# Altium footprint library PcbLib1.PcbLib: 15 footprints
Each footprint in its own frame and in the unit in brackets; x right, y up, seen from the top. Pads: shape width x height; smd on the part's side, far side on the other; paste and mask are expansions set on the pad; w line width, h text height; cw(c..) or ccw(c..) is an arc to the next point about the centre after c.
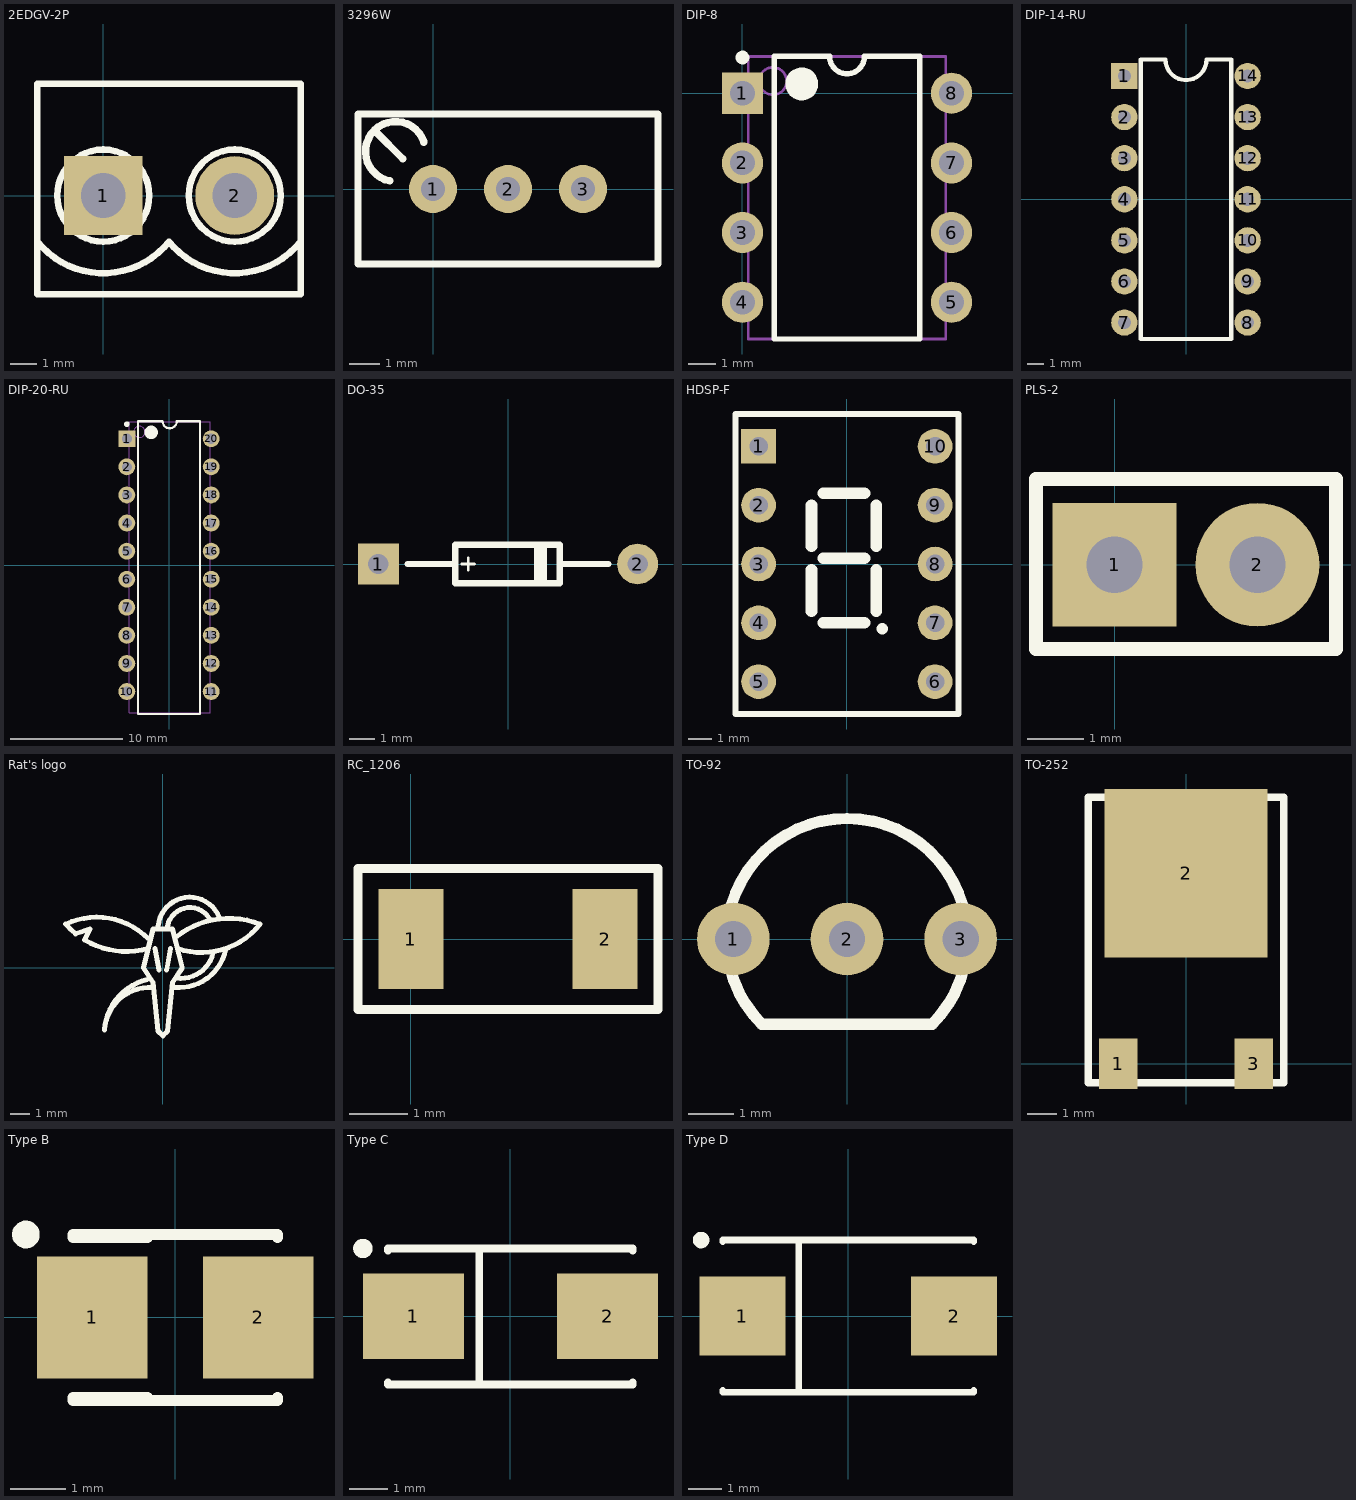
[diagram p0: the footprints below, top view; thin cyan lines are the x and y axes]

## 2EDGV-2P [mm]
height 10
pads (2):
  rect 3x3 hole 1.7: 1(0,0)
  round 3 hole 1.7: 2(5,0)
Top Overlay:
  circle w0.25: c0,0 r1.75
  circle w0.25: c5,0 r1.75
  lines w0.25: -2.5,-3.75 7.5,-3.75 7.5,4.25 -2.5,4.25 -2.5,-3.75
  lines w0.254: -2.499,-1.752 ccw(c0,0.25) 2.499,-1.752 ; 2.501,-1.752 ccw(c5,0.25) 7.499,-1.752
3D body: height 10.22, standoff -2.17, extent -2.725,-3.8 7.525,4

## 3296W [mm]
height 10
pads (3):
  round 1.6 hole 0.8: 1(0,0) 2(2.5,0) 3(5,0)
Top Overlay:
  lines w0.25: -1.905,1.905 -1,1 ; -1.446,0.269 cw(c-1.25,1.25) -0.301,1.566 ; -2.5,-2.5 7.5,-2.5 7.5,2.5 -2.5,2.5 -2.5,-2.5
3D body: height 11.55, standoff -7.62, extent -2.265,-2.415 7.265,2.415

## DIP-8 [mm] "DIP; 8 Leads; Row Spacing 7.62 mm; Pitch 2.54 mm"
height 5.08
pads (8):
  rect 1.5x1.5 hole 0.9: 1(0,0)
  round 1.5 hole 0.9: 2(0,-2.54) 3(0,-5.08) 4(0,-7.62) 5(7.62,-7.62) 6(7.62,-5.08) 7(7.62,-2.54) 8(7.62,0)
Top Overlay:
  circle w0.25: c0,1.3 r0.125
  circle w0.6: c2.16,0.34 r0.3
  lines w0.2: 1.16,-8.96 1.16,1.34 3.175,1.34 ccw(c3.81,1.34) 4.445,1.34 6.46,1.34 6.46,-8.96 1.16,-8.96
Mechanical 13:
  circle w0.1: c1.11,0.44 r0.5
  lines w0.1: 0.21,-8.96 0.21,1.34 7.41,1.34 7.41,-8.96 0.21,-8.96
3D body: height 5.08, standoff -3.5, extent -0.125,-9.27 7.745,1.65

## DIP-14-RU [mm]
height 5
pads (14):
  rect 1.6x1.6 hole 0.8: 1(-3.75,7.5)
  round 1.6 hole 0.8: 2(-3.75,5) 3(-3.75,2.5) 4(-3.75,0) 5(-3.75,-2.5) 6(-3.75,-5) 7(-3.75,-7.5) 8(3.75,-7.5) 9(3.75,-5) 10(3.75,-2.5) 11(3.75,0) 12(3.75,2.5) 13(3.75,5) 14(3.75,7.5)
Top Overlay:
  lines w0.25: -1.25,8.5 -2.75,8.5 -2.75,-8.5 2.75,-8.5 2.75,8.5 1.25,8.5
  lines w0.254: -1.25,8.5 ccw(c0,8.5) 1.25,8.5
3D body: height 4.5, standoff -3.5, extent -3.88,-9.05 3.88,9.05

## DIP-20-RU [mm]
height 5
pads (20):
  rect 1.5x1.5 hole 0.9: 1(-3.75,11.25)
  round 1.5 hole 0.9: 2(-3.75,8.75) 3(-3.75,6.25) 4(-3.75,3.75) 5(-3.75,1.25) 6(-3.75,-1.25) 7(-3.75,-3.75) 8(-3.75,-6.25) 9(-3.75,-8.75) 10(-3.75,-11.25) 11(3.75,-11.25) 12(3.75,-8.75) 13(3.75,-6.25) 14(3.75,-3.75) 15(3.75,-1.25) 16(3.75,1.25) 17(3.75,3.75) 18(3.75,6.25) 19(3.75,8.75) 20(3.75,11.25)
Top Overlay:
  circle w0.25: c-3.75,12.55 r0.125
  circle w0.6: c-1.59,11.82 r0.3
  lines w0.2: -2.75,-13.25 -2.75,12.82 -0.575,12.82 ccw(c0.06,12.82) 0.695,12.82 2.75,12.82 2.75,-13.25 -2.75,-13.25
Mechanical 13:
  circle w0.1: c-2.64,11.87 r0.5
  lines w0.1: -3.54,-13.13 -3.54,12.77 3.66,12.77 3.66,-13.13 -3.54,-13.13
3D body: height 4.5, standoff -3.5, extent -3.82,-12.98 3.94,12.62

## DO-35 [mm]
height 2
pads (2):
  rect 1.6x1.6 hole 0.8: 1(-5.084,0)
  round 1.6 hole 0.8: 2(5.084,0)
Top Overlay:
  region: 1.024,-0.75 1.524,-0.75 1.524,0.75 1.024,0.75
  lines w0.1: -1.813,0 -1.314,0 ; -1.563,-0.25 -1.563,0.25
  lines w0.25: -3.937,0 -2.064,0 ; 2.044,0 3.937,0 ; -2.064,-0.75 -2.064,0.75 2.032,0.75 2.032,-0.75 -2.064,-0.75
3D body: height 2.15, standoff -2.54, extent -5.35,-0.889 5.343,0.864

## HDSP-F [mm]
height 5.08
pads (10):
  rect 1.5x1.5 hole 0.8: 1(-3.81,5.08)
  round 1.5 hole 0.8: 2(-3.81,2.54) 3(-3.81,0) 4(-3.81,-2.54) 5(-3.81,-5.08) 6(3.81,-5.08) 7(3.81,-2.54) 8(3.81,0) 9(3.81,2.54) 10(3.81,5.08)
Top Overlay:
  lines w0.25: -4.81,-6.477 4.826,-6.477 4.826,6.477 -4.81,6.477 -4.81,-6.477
  lines w0.5: -1.524,-2.032 -1.524,-0.254 ; -1.524,0.762 -1.524,2.54 ; -1.016,-2.54 0.762,-2.54 ; -1.016,0.254 0.762,0.254 ; -1.016,3.048 0.762,3.048 ; 1.27,-2.032 1.27,-0.254 ; 1.27,0.762 1.27,2.54 ; 1.524,-2.794 1.525,-2.794
3D body: height 7, standoff -3, extent -4.8,-6.5 4.8,6.5

## PLS-2 [mm]
height 5
pads (2):
  rect 2.2x2.2 hole 1: 1(0,0)
  round 2.2 hole 1: 2(2.54,0)
Top Overlay:
  lines w0.25: -1.397,-1.5 -1.397,1.524 3.937,1.524 3.937,-1.5 -1.397,-1.5
3D body: height 8.54, standoff -3, extent -1.27,-1.27 3.81,1.27

## Rat's logo [mm]
Top Overlay:
  lines w0.254: -4.516,1.786 cw(c-1.875,5.025) -5,2.25 cw(c-3.402,-1.109) -0.75,1.5 ; -4.5,1.75 -3.75,2 -4,1.5 ; -4.033,1.446 ccw(c-1.875,5.025) -0.75,1 ; -0.8,-0.6 ccw(c-0.153,-3.378) -3,-3.2 cw(c-0.65,-3.35) -0.5,-1 ; -0.4,1 -0.2,-0.1 ; -0.238,2.147 cw(c1.384,2.012) 2.9,2.6 ; 0.2,-0.1 0.4,1 ; 0.239,2.148 cw(c1.394,1.929) 2.395,2.546 ; 0.6,-1 ccw(c0.831,1.445) 3.23,0.923 ; 0.652,1.562 cw(c3.411,-1.797) 5,2.25 cw(c2,4.6) 0.75,1 ; 0.711,-0.52 ccw(c0.937,1.169) 2.6,0.8 ; -1,0 -0.5,-0.75 -0.25,-3.25 0,-3.5 0.25,-3.25 0.5,-0.75 1,0 0.5,2 -0.5,2 -1,0

## RC_1206 [mm]
height 1.5
pads (2):
  rect 1.1x1.7 smd: 1(0,0) 2(3.3,0)
Top Overlay:
  lines w0.15: -0.9,-1.2 -0.9,1.2 4.2,1.2 4.2,-1.2 -0.9,-1.2
3D body: height 1, standoff 0, extent 0.05,-0.8 3.25,0.8

## TO-92 [mm]
height 5
pads (3):
  round 1.6 hole 0.8: 1(-2.5,0) 2(0,0) 3(2.5,0)
Top Overlay:
  lines w0.25: -1.875,-1.875 cw(c0,0) 1.875,-1.875 -1.875,-1.875
3D body: height 9.7, standoff -2.7, extent -2.798,-1.746 2.798,2.184

## TO-252 [mm]
height 2.3
pads (3):
  rect 1.3x1.7 smd: 1(-2.285,0) 3(2.285,0)
  rect 5.5x5.7 smd: 2(0,6.44)
Top Overlay:
  lines w0.254: -3.302,-0.635 3.302,-0.635 3.302,9.017 -3.302,9.017 -3.302,-0.635
3D body: height 2.3, standoff 0, extent -3.29,-0.647 3.29,9.053

## Type B [mm]
height 2.5
pads (2):
  rect 2x2.2 smd: 1(-1.5,0) 2(1.5,0)
Top Overlay:
  circle w0.25: c-2.7,1.5 r0.125
  lines w0.2: -1.85,-1.5 1.85,-1.5 1.85,-1.45 ; -1.85,-1.45 -0.5,-1.45 ; -1.85,1.45 -0.5,1.45 ; -1.85,1.5 1.85,1.5 1.85,1.45
3D body: height 1.89, standoff -0.02, extent -1.831,-1.4 1.832,1.4

## Type C [mm]
height 3.4
pads (2):
  rect 2.6x2.2 smd: 1(-2.5,0) 2(2.5,0)
Top Overlay:
  circle w0.25: c-3.8,1.75 r0.125
  lines w0.2: -3.15,-1.7 -3.15,-1.75 3.15,-1.75 3.15,-1.7 ; -3.15,1.7 -3.15,1.75 3.15,1.75 3.15,1.7 ; -0.8,-1.75 -0.8,1.75
3D body: height 2.79, standoff -0.04, extent -3.799,-1.8 3.799,1.713

## Type D [mm]
height 3.7
pads (2):
  rect 2.6x2.4 smd: 1(-3.2,0) 2(3.2,0)
Top Overlay:
  circle w0.25: c-4.45,2.3 r0.125
  lines w0.2: -3.8,-2.25 -3.8,-2.3 3.8,-2.3 3.8,-2.25 ; -3.8,2.25 -3.8,2.3 3.8,2.3 3.8,2.25 ; -1.5,-2.3 -1.5,2.3
3D body: height 3, standoff 0, extent -3.7,-2.225 3.7,2.225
